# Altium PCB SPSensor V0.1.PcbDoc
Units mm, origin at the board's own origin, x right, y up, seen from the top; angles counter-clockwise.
Board outline 19.98 x 57.97 mm, 4 copper layers (TopLayer, GND, PWR, BottomLayer); 75 components, 49 nets, 242 pads, 80 vias.
Unrouted connection lines stored in the file: 11.
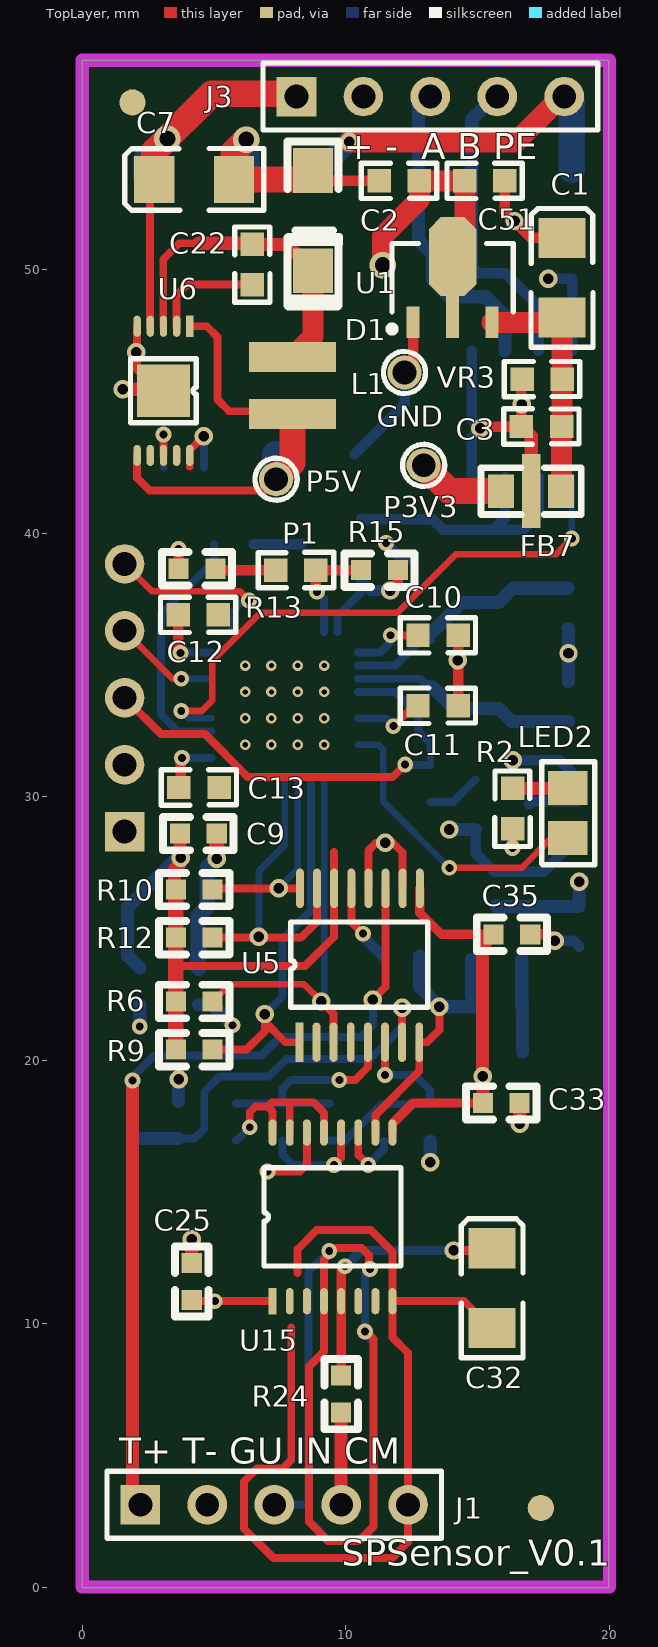
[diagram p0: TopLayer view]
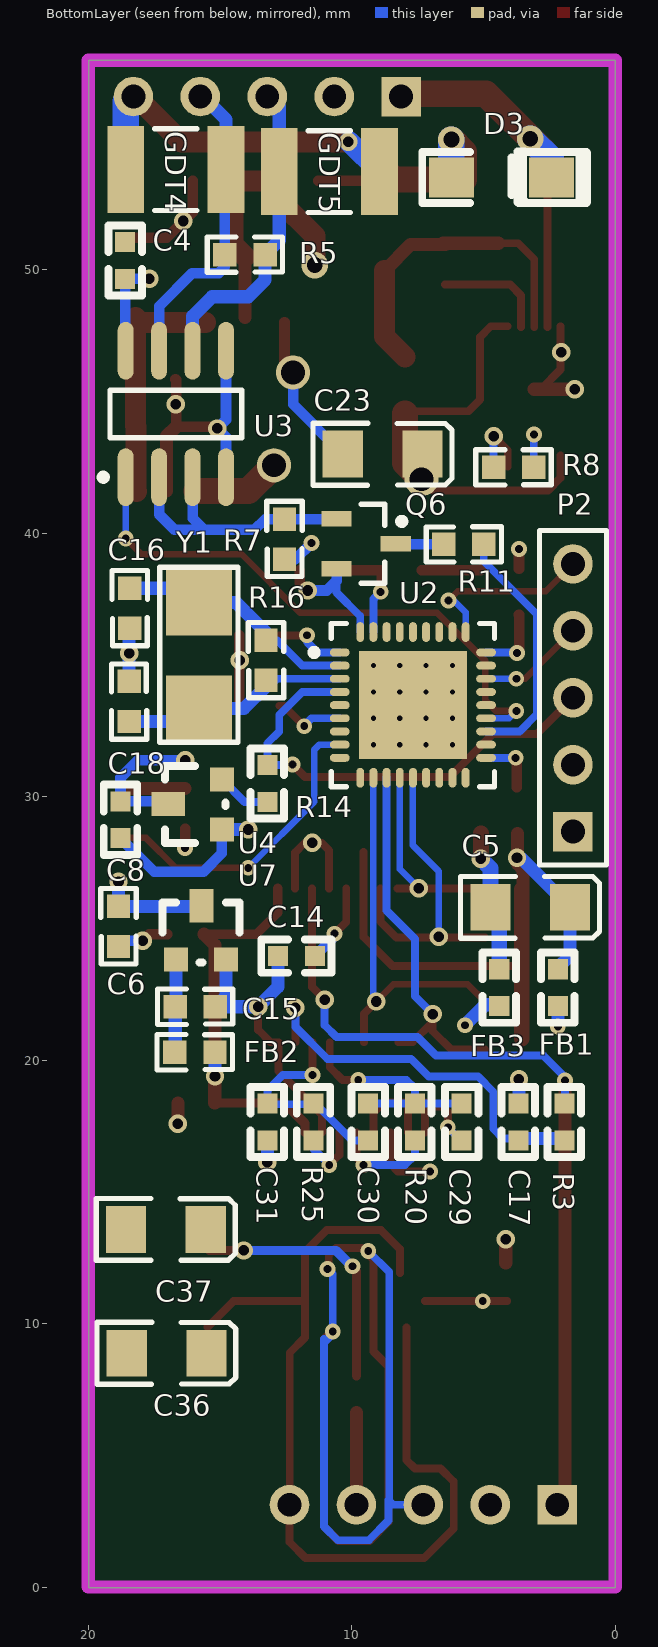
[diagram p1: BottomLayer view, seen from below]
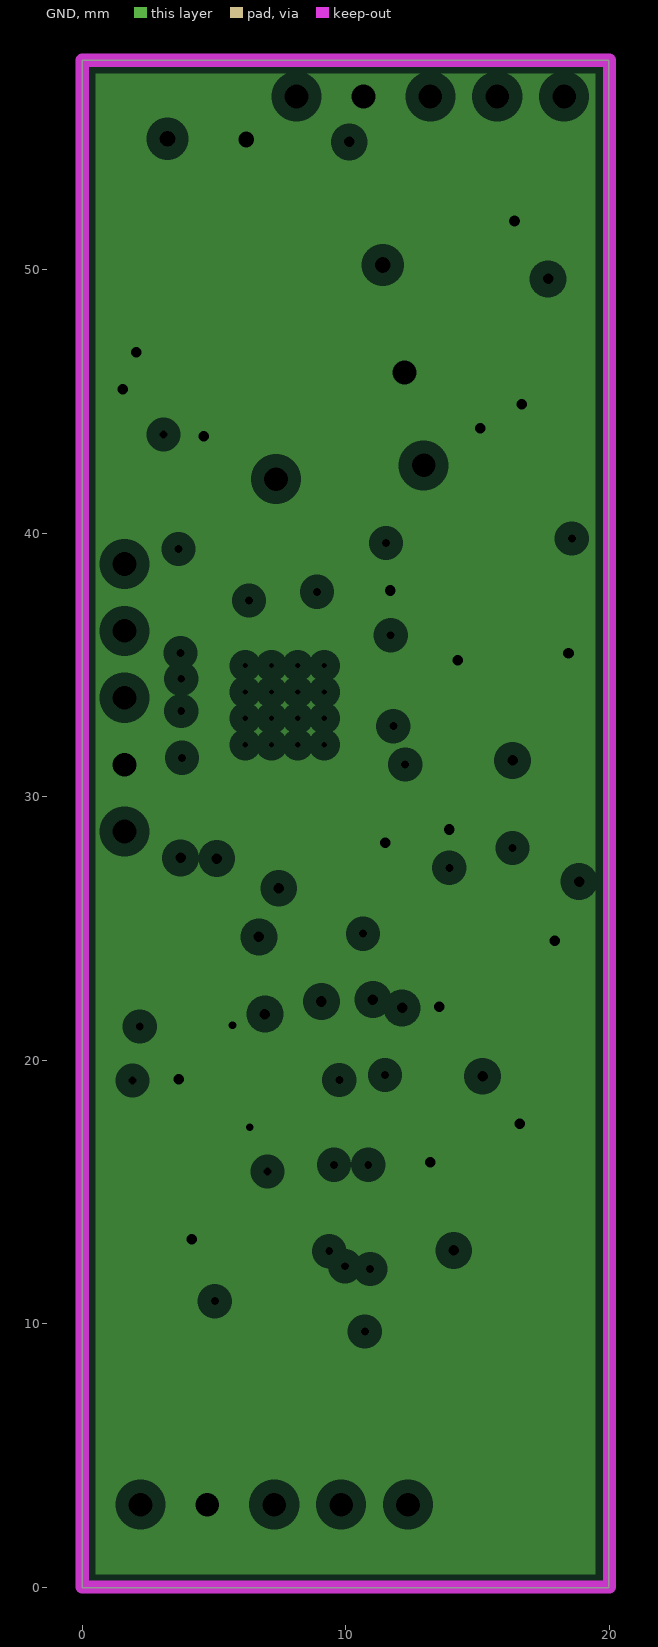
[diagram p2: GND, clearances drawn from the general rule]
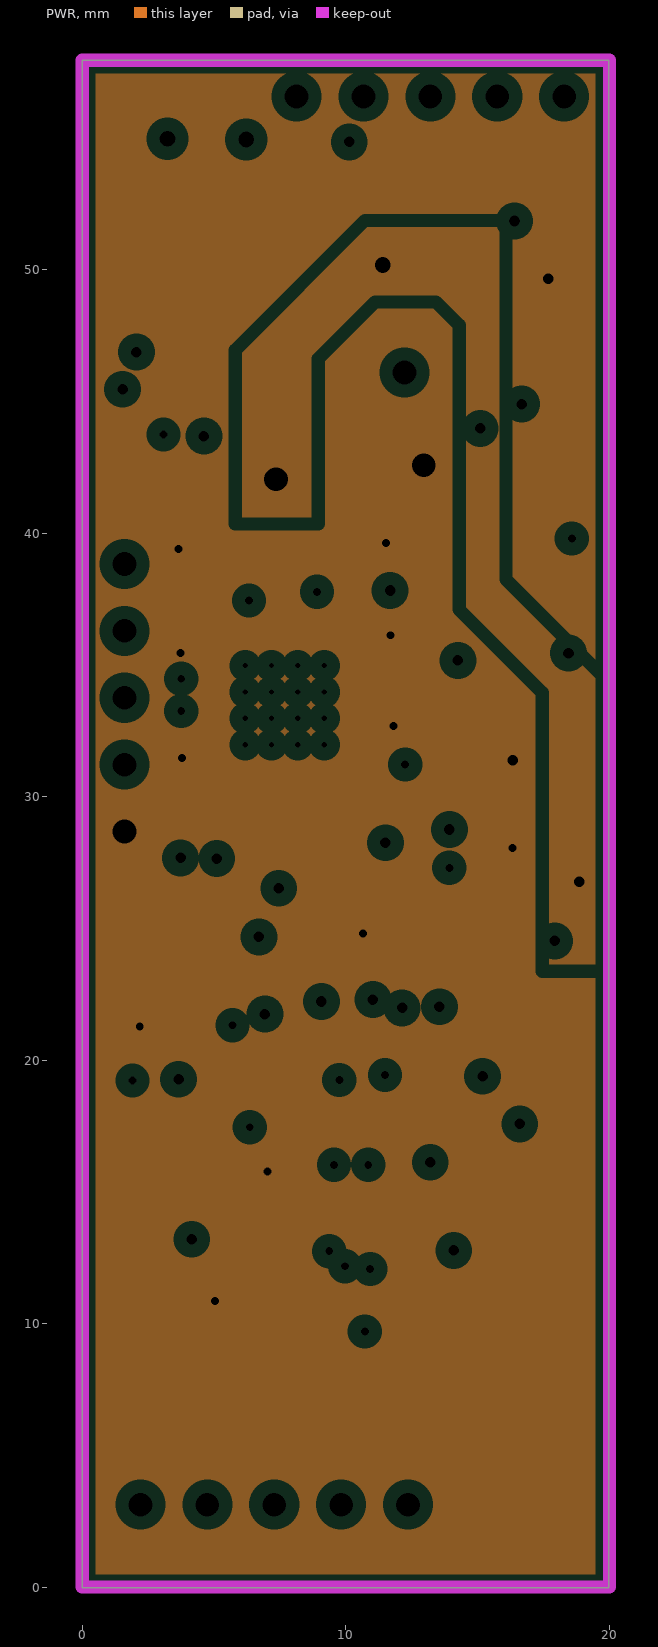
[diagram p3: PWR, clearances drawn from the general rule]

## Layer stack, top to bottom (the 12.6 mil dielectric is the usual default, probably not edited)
TopLayer: signal copper 0.0356
Dielectric: core 0.32, FR-4, Dk 4.8
GND: plane copper 0.0356, net GND
Dielectric: prepreg 0.32, FR-4, Dk 4.8
PWR: plane copper 0.0356, net VCC3.3
Dielectric: core 0.32, FR-4, Dk 4.8
BottomLayer: signal copper 0.0356

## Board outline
-0.006,-0.025 19.975,-0.025 19.975,57.95 -0.006,57.95

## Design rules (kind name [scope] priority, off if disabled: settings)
Clearance Clearance_poly [InPolygon] p1: gap=0.3
Clearance [All] p2: gap=0.15
ComponentClearance [All] p1: gap=0.15 collisioncheckmode=3 verticalgap=0.254 showdistances=FALSE
FabricationTestPointUsage TestPointUsage [All] p1: valid=0 allowmultiple=FALSE
FabricationTestpoint Testpoint [All] p1: side=3 testpointundercomponent=TRUE minsize=1.016 maxsize=2.54 preferedsize=1.524 minholesize=0.508 maxholesize=1.016 preferedholesize=0.813 testpointgrid=0.025 allowsidetop=TRUE allowsidebottom=TRUE usegrid=TRUE gridtolerance=0
HoleSize [All] p1: absolutevalues=TRUE maxlimit=5.08 minlimit=0.025 maxpercent=80.000 minpercent=20.000
MinimumSolderMaskSliver [All] p1: minsoldermaskwidth=0.15
PlaneClearance [All] p1: clearance=0.5
PlaneConnect [All] p1: planeconnectstyle=Relief reliefexpansion=0.5 reliefentries=4 reliefconductorwidth=0.3 reliefairgap=0.3
PolygonConnect PolygonConnect_via [IsVia] p1: connectstyle=Direct reliefconductorwidth=0.254 reliefentries=4 polygonreliefangle="90 Angle"
PolygonConnect [All] p2: connectstyle=Relief reliefconductorwidth=0.3 reliefentries=4 polygonreliefangle="90 Angle"
RoutingVias [All] p1: holewidth=0.305 width=0.61 viastyle="Through Hole" minholewidth=0.254 minwidth=0.508 maxholewidth=2 maxwidth=5
SilkToSilkClearance [All] p1: silktosilkclearance=0
SilkscreenOverComponentPads [All] p1: minsilkscreentomaskgap=0
SolderMaskExpansion [All] p1: expansion=0.102
Width [All] p1: maxlimit=5.08 minlimit=0.1 preferedwidth=0.254
19 further rules are at their usual default settings.

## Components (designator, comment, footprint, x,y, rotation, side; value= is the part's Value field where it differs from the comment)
C1 "10uF" SM1206 18.2,49.7 r90 top
C2 "1uF" SM0603 12.025,53.425 r0 top
C3 "1uF" SM0603 17.425,44.1 r0 top
C4 "0.1uF" 0603A 18.6,49.65 r90 bottom
C5 "10uF" SM1206 3.225,25.8 r180 bottom
C6 "0.47uF" SM0603 18.8,25.075 r270 bottom
C7 "4.7uF/50V" SM1206 4.235,53.425 r180 top
C8 "0.1uF" 0603A 18.775,29.822 r270 bottom
C9 "0.1uF" 0603A 3.7,28.6 r0 top
C10 "0.1uF" SM0603 13.5,36.175 r0 top
C11 "0.1uF" SM0603 13.5,33.5 r0 top
C12 "0.1uF" SM0603 4.4,36.95 r0 top
C13 "0.1uF" SM0603 4.425,30.4 r0 top
C14 "0.1uF" 0603A 11.4,23.95 r0 bottom
C15 "0.1uF" SM0603 15.935,22.075 r180 bottom
C16 "22pF" SM0603 18.375,37.15 r270 bottom
C17 "1uF" 0603A 3.675,16.953 r90 bottom
C18 "22pF" SM0603 18.5,33.615 r90 bottom
C22 "0.47uF" SM0603 6.4,50.2 r90 top
C23 "22uF" SM1206 8.825,43 r180 bottom
C25 "0.1uF" 0603A 4.15,10.9 r90 top
C29 "0.1uF" 0603A 5.825,16.953 r90 bottom
C30 "100pF" 0603A 9.375,18.35 r270 bottom
C31 "0.1uF" 0603A 13.2,18.35 r270 bottom
C32 "1nF/2kV" SM1206 15.55,11.35 r90 top
C33 "0.1uF" 0603A 15.2,18.375 r0 top
C35 "0.1uF" 0603A 15.6,24.775 r0 top
C36 "1nF/2kV" SM1206 17.025,8.875 r180 bottom
C37 "1nF/2kV" SM1206 17.05,13.575 r180 bottom
C51 "0.1uF" SM0603 15.275,53.425 r0 top
D1 "CD1607-B140" 1206D 8.75,53.575 r270 top
D3 "M7" 1206D 6.025,53.5 r180 bottom
FB1 "BLM18PG600SN1" 0603A 2.175,22.053 r90 bottom
FB2 "BLM18PG600SN1" SM0603 15.95,20.35 r180 bottom
FB3 "BLM18PG600SN1" 0603A 4.4,22.053 r90 bottom
FB7 "NFM21PC105B1C3" NFM21PC105 18.175,41.6 r180 top
GDT4 "SMD1812-091" 1812 16.675,53.8 r0 bottom
GDT5 "SMD1812-091" 1812 10.85,53.725 r0 bottom
GND "TestPoint" "test point" 12.225,46.1 r90 top
J1 "Header 5" HDR1X5 2.2,3.125 r0 top
J3 "Header 5" HDR1X5 8.125,56.575 r0 top
L1 "LPS3010-472ML" LPS3010 7.975,46.69 r270 top
LED2 "RUN" SM0805 18.4,29.4 r270 top
P1 "NC" sm0603 8.1,38.55 r180 top
P2 "Header 5" HDR1X5 1.6,28.675 r90 bottom
P3V3 "TestPoint" "test point" 12.95,42.575 r90 top
P5V "TestPoint" "test point" 7.35,42.05 r90 top
Q6 "MMBT3904" SOT23_N 9.45,39.6 r180 bottom
R2 "560R" SM0603 16.275,29.55 r90 top
R3 "10K" 0603A 1.925,18.35 r270 bottom
R5 "120R" SM0603 14.05,50.625 r180 bottom
R6 "100K" 0603A 3.545,22.225 r0 top
R7 "4.7K" SM0603 12.5,39.775 r270 bottom
R8 "49.9K" SM0603 3.85,42.55 r180 bottom
R9 "100K" 0603A 3.545,20.4 r0 top
R10 "100K" 0603A 3.545,26.475 r0 top
R11 "1K" SM0603 5.75,39.525 r0 bottom
R12 "100K" 0603A 3.545,24.65 r0 top
R13 "1K" 0603A 3.65,38.65 r0 top
R14 "1K" 0603A 13.2,29.8 r90 bottom
R15 "100K" 0603A 11.975,38.6 r180 top
R16 "1M" SM0603 13.2,35.175 r270 bottom
R20 "1K" 0603A 7.6,16.953 r90 bottom
R24 "1K" 0603A 9.82,6.625 r90 top
R25 "1K" 0603A 11.45,16.953 r90 bottom
U1 "RT9166A-33PXL" SOT89L 14.05,49.7 r90 top
U2 "STM32F103T8U6" VFQN36_V 7.675,33.475 r180 bottom
U3 "MAX3485CSA" NSO8_N 16.675,44.525 r90 bottom
U4 "CAT809VTBI-GT3" SOT-23 17.075,31.086 r90 bottom
U5 "AD7793BRU" AD7793 10.52,23.6 r90 top
U6 "LT3971IMSE-5" LT3971 3.075,45.405 r180 top
U7 "AD1584B" SOT-23 14.339,25.975 r180 bottom
U15 "LMP91200" LMP91200 9.495,14.05 r0 top
VR3 "V3.5MLA0603N" SM0603 17.45,45.9 r0 top (schematic designator VA2)
Y1 "8MHz" CY5.4X4.6 15.8,37.35 r270 bottom

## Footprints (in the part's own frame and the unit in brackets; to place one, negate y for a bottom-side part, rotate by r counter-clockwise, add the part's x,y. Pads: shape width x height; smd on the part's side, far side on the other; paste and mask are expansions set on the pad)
0603A [mil]
  rect 30x30 smd: 1(0,0) 2(55,0)
  silkscreen extent -25,-25 80,25
1206D [mm]
  rect 1.7x1.524 smd: 1(-0.19,0.003) 2(3.61,0.003)
  silkscreen extent -1.3,-0.97 4.96,0.99
1812 [mm] "Chip Capacitor, Body 4.5x3.2mm, IPC High Density"
  rect 1.4x3.3 smd: 1(-1.9,0) 2(1.9,0)
  silkscreen extent -0.8,-1.55 0.8,1.55, body extent -2.4,-1.7 2.4,1.7, height 1.4
AD7793 [mm]
  rect 1.5x0.3 smd: 1(-2.921,2.286)
  oval 1.5x0.3 smd: 2(-2.921,1.636) 3(-2.921,0.986) 4(-2.921,0.336) 5(-2.921,-0.314) 6(-2.921,-0.964) 7(-2.921,-1.614) 8(-2.921,-2.264) 9(2.921,-2.286) 10(2.921,-1.636) 11(2.921,-0.986) 12(2.921,-0.336) 13(2.921,0.314) 14(2.921,0.964) 15(2.921,1.614) 16(2.921,2.264)
  silkscreen extent -1.59,-2.59 1.64,2.61
CY5.4X4.6 [mm]
  rect 2.5x2.5 smd: 1(-0.025,0) 2(4,0)
  silkscreen extent -1.35,-1.49 5.28,1.49
HDR1X5 [mm] "Connector; Header; 5 Position"
  rect 1.5x1.5 hole 0.9: 1(0,0)
  round 1.5 hole 0.9: 2(2.54,0) 3(5.08,0) 4(7.62,0) 5(10.16,0)
  silkscreen extent -1.27,-1.27 11.43,1.27
LMP91200 [mm]
  rect 0.3x1 smd: 1(-2.275,-3.2)
  oval 0.3x1 smd: 2(-1.625,-3.2) 3(-0.975,-3.2) 4(-0.325,-3.2) 5(0.325,-3.2) 6(0.975,-3.2) 7(1.625,-3.2) 8(2.275,-3.2) 9(2.275,3.2) 10(1.625,3.2) 11(0.975,3.2) 12(0.325,3.2) 13(-0.325,3.2) 14(-0.975,3.2) 15(-1.625,3.2) 16(-2.275,3.2)
  silkscreen extent -2.6,-1.87 2.6,1.87
LPS3010 [mm]
  rect 1.14x3.3 smd: 1(0,0) 2(2.16,0)
LT3971 [mm]
  rect 0.28x0.8 smd: 1(-1,-2.45)
  oval 0.28x0.8 smd: 2(-0.5,-2.45) 3(0,-2.45) 4(0.5,-2.45) 5(1,-2.45) 6(1,2.45) 7(0.5,2.45) 8(0,2.45) 9(-0.5,2.45) 10(-1,2.45)
  rect 2x2 smd: 11(0,0)
  silkscreen extent -1.25,-1.21 1.25,1.22
NFM21PC105 [mm]
  rect 1x1.27 smd: 1(0.01,0.008) 2(2.286,0)
  rect 0.7x2.8 smd: 3(1.143,0)
  silkscreen extent -0.76,-0.89 3.05,0.89
NSO8_N [mm] "SOIC, 8-Leads, Body 4.9x3.9mm, Pitch 1.27mm, IPC Medium Density"
  oval 2.2x0.6 smd: 1(-2.4,1.905) 2(-2.4,0.635) 3(-2.4,-0.635) 4(-2.4,-1.905) 5(2.4,-1.905) 6(2.4,-0.635) 7(2.4,0.635) 8(2.4,1.905)
  silkscreen extent -2.52,-2.5 0.9,2.88, body extent -2,-2.5 2,2.5, height 1.75
SM0603 [mil]
  rect 35x35 smd: 1(-30,-2) 2(30,-2)
  silkscreen extent -57,-28 56,24
sm0603 [mil]
  rect 35x35 smd: 1(-30,-2) 2(30,-2)
  silkscreen extent -57,-28 56,24
SM0805 [mm]
  rect 1.3x1.5 smd: 1(-0.933,0.022) 2(0.967,0.022)
  silkscreen extent -1.93,-0.97 1.98,1.04
SM1206 [mil]
  rect 60x70 smd: 1(59.5,0) 2(-59.5,0)
  silkscreen extent -104,-46 104,46
SOT23_N [mm] "SOT23, 3-Leads, Body 2.9x1.3mm, Pitch 0.95mm, Lead Span 2.3mm - Reverse Pinning, IPC Medium Density"
  rect 1.15x0.6 smd: 1(1.125,0) 2(-1.125,-0.95) 3(-1.125,0.95)
  silkscreen extent -0.2,-1.5 1.47,1.5, body extent -0.7,-1.5 0.7,1.5, height 1.1
SOT89L [mm] "SOT89, 3-Leads, Body 4.5x2.4 mm, Pitch 1.5mm, Lead Span 4.1mm, IPC High Density"
  rect 1.2x0.5 smd: 1(-1.7,1.5) 3(-1.7,-1.5)
  rect 1.6x0.5 smd: 2(-1.5,0)
  oct 3x1.8 smd: 2(0.8,0)
  silkscreen extent -2.07,-2.3 1.3,2.42, body extent -1.3,-2.3 1.3,2.3, height 1.6
SOT-23 [mil]
  rect 36x36 smd: 1(-91.86,-84.66) 2(-16.86,-84.66)
  rect 36x50 smd: 3(-53.86,-4.66)
  silkscreen extent -112,-90 3,0
"test point" [mm]
  round 1.3 hole 0.9: 1(0,0)
  silkscreen extent -0.8,-0.8 0.8,0.8
VFQN36_V [mm] "QFN, 36-Leads, Body 6x6mm, Pitch 0.5mm, ST Recommended"
  oval 0.75x0.3 smd: 1(-2.775,2) 2(-2.775,1.5) 3(-2.775,1) 4(-2.775,0.5) 5(-2.775,0) 6(-2.775,-0.5) 7(-2.775,-1) 8(-2.775,-1.5) 9(-2.775,-2) 19(2.775,-2) 20(2.775,-1.5) 21(2.775,-1) 22(2.775,-0.5) 23(2.775,0) 24(2.775,0.5) 25(2.775,1) 26(2.775,1.5) 27(2.775,2)
  oval 0.3x0.75 smd: 10(-2,-2.755) 11(-1.5,-2.755) 12(-1,-2.755) 13(-0.5,-2.755) 14(0,-2.755) 15(0.5,-2.755) 16(1,-2.755) 17(1.5,-2.755) 18(2,-2.755) 28(2,2.775) 29(1.5,2.775) 30(1,2.775) 31(0.5,2.775) 32(0,2.775) 33(-0.5,2.775) 34(-1,2.775) 35(-1.5,2.775) 36(-2,2.775)
  rect 4.1x4.1 smd: 37(0,0)
  silkscreen extent -3.88,-3.1 3.1,3.1, body extent -3.05,-3.05 3.05,3.05, height 1

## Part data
C1 C2 C3 C10 C11 C12 C13 C16 C18: library part Cap, "Capacitor"
C4 C8: library part Cap, "Capacitor, X7R Ceramic"
C5: library part CAPE, "¼«Ð"
C6 C9 C14 C15 C22 C25 C29 C30 C31 C32 C33 C35 C36 C37 C51: library part CAP, "Capacitor"
C7 C23: library part C, "¼«Ð"
C17: library part CAP, "电?"
D1: library part DIODE, "Diode"
D3: library part "Diode 1N4007", "1 Amp General Purpose Rectifier"
FB1 FB3 L1: library part INDUCTOR
FB2 FB7: library part Inductor, "Inductor"
GDT4 GDT5: library part BT90
J1 J3 P2: "Header, 5-Pin"
LED2: library part LED0, "Typical INFRARED GaAs LED"
P1: library part Header, "Header, 2-Pin, 2.54mm, 排?"
Q6: "NPN Switching Transistor"
R2 R5 R7 R11 R16: library part Res2, "Resistor"
R3 R6 R9 R10 R12 R20 R24 R25: library part RES, "电?"
R8 R13 R14 R15: library part RE, "电?"
U1: library part "Header 3", "Header, 3-Pin"
U2: "STM32 ARM-based 32-bit MCU with 64 Kbytes Flash, 36-pin VFQFPN, Industrial Temperature"
U3: library part MAX485CSA, "Low-Power, Slew-Rate-Limited RS-485/RS-422 Transceiver"
U4: library part CAT809-SOT, "Onsemi"
U5: library part AD7793
U6: library part LT3971
U7: library part "Header 3", "4.096V reference"
VR3: library part "D Zener", "Zener Diode"
Y1: library part XTAL, "Crystal Oscillator"

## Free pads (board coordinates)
  round 1 smd: 0(1.9,56.35) 0(17.4,3)

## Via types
v1: diameter 0.7, hole 0.4, TopLayer to BottomLayer, 31 vias
v2: diameter 0.6, hole 0.3, TopLayer to BottomLayer, 30 vias
v3: diameter 0.4, hole 0.2, TopLayer to BottomLayer, tented top, 16 vias
v4: diameter 1, hole 0.6, TopLayer to BottomLayer, 3 vias

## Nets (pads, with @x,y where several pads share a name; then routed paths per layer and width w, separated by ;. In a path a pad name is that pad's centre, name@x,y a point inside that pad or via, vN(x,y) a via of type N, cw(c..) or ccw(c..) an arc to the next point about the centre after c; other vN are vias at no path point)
+24V: C7.1 D3.2 J3.1 U6.4 | length 14.8
  TopLayer w0.3: U6.4@2.569,47.823 2.569,53.27 C7.1
  TopLayer w1: C7.1 2.724,54.499 4.9,56.675 J3.1@8.125,56.675
  BottomLayer w1: D3.2 2.415,54.165 v4(3.225,54.975)
BOOT0: P1.1 R15.2 U2.35 | length 4.1
  TopLayer w0.4: v2@8.862,37.813 P1.1 R15.2@10.577,38.601
  BottomLayer w0.3: v2(8.9,37.775) 9.175,37.5 U2.35
DVDD: C5.1 C9.1 FB1.2 R6.1 R9.1 R10.1 R12.1 U5.14 | length 22.8
  TopLayer w0.3: 3.545,23.575 8.45,23.575 9.556,24.681 U5.14 9.556,27.894
  TopLayer w0.5: R10.1 3.5,26.519 3.5,27.25 3.7,27.45 C9.1
  TopLayer w0.6: 3.545,20.825 3.545,23.575 R10.1
  BottomLayer w0.5: FB1.2@2.175,23.5 1.714,23.961 C5.1 3.589,27.675 v1(3.725,27.675)
EARTH: GDT4.2 GDT5.1 J3.5 | length 13.5
  TopLayer w0.8: v1(10.125,54.85) 16.46,54.85 J3.5@18.285,56.675
  BottomLayer w0.8: GDT5.1 v1@10.075,54.85
  BottomLayer w1: J3.5@18.285,56.675 18.575,56.385 GDT4.2
GND: C1.1 C2.1 C3.1 C4.2 C6.2 C7.2 C8.2 C10.2 C11.2 C12.2 C13.2 C14.2 C15.2 C16.2 C17.2 C18.2 C23.2 C25.2 C29.1 C31.2 C33.2 C35.2 C36.2 C37.2 C51.2 D1.1 D3.1 FB3.1 FB7.3 GND.1 J1.2 J3.2 P2.2 Q6.2 R8.1 R15.1 U1.1 U2.5 U2.17 U2.18 U2.26 U2.36 U3.4 U3.5 U4.1 U5.8 U5.10 U5.12 U6.5 U6.10 U6.11 U7.2 U15.10 U15.13 U15.15 U15.16 VR3.1 | length 83.4
  TopLayer w0.3: U6.5 2.075,46.216 U6.11@2.825,45.465 ; 4.075,42.53 U6.10 4.075,43.15 v1(4.612,43.687) ; v2(6.35,17.451) 6.35,18.025 6.558,18.233 7.033,18.233 ; U15.16 7.22,18.047 7.033,18.233 ; U15.15 7.87,18.325 7.795,18.4 ; U15.13 9.17,18 8.77,18.4 7.795,18.4 ; U5.12 10.856,27.956 11.15,28.25 v1(11.5,28.25) 11.781,28.25 12.156,27.875 U5.10 ; U15.10 11.12,17.92 12.784,19.584 U5.8 13.079,20.679 13.55,21.15 v1(13.55,22.025) ; 7.033,18.233 7.2,18.4 7.795,18.4
  TopLayer w0.4: D1.1 9.144,53.374 C2.1 ; v1(11.675,37.825) 11.975,38.125 R15.1 ; GND.1 12.55,46.425 U1.1 ; C11.2 C10.2 ; v1(15.1,43.975) 15.174,44.049 C3.1 16.663,45.824 VR3.1 ; C51.2 16.037,52.188 17.014,51.211 C1.1 ; C35.2 17.675,24.775 v1(17.925,24.525)
  TopLayer w0.5: v1@1.487,45.465 v1(1.525,45.465) 2.825,45.465 U6.11@3.069,45.465 ; C25.2 v1(4.15,13.2) ; v1(16.597,17.578) C33.2 ; C3.1 17.032,43.68 FB7.3
  TopLayer w1: v4(6.215,54.94) 5.747,54.472 C7.2 8.412,53.425 D1.1
  BottomLayer w0.3: R8.1 v1(4.612,43.687) ; C29.1 5.852,16.953 v2(6.35,17.451) ; U2.36 9.675,36.85 10.575,37.75 10.575,38.2
  BottomLayer w0.4: C23.2 12.225,44.889 GND.1 ; Q6.2 10.575,38.2 10.95,37.825 v1(11.675,37.825) ; U3.4 14.77,43.645 v1(15.1,43.975) 14.77,44.305 U3.5 ; U4.1 14.925,27.85 15.625,27.15 17.5,27.15 C8.2 ; v1(17.925,24.525) 18.639,24.525 C6.2
  BottomLayer w0.5: C17.2@3.65,18.425 v1(3.65,19.275) ; FB3.1@4.4,22.1 4.925,22.1 v2(5.7,21.325) ; C14.2 12.797,22.778 v1(13.55,22.025) C15.2@15.172,22.025 ; v1(13.2,16.125) C31.2@13.2,16.925 ; v1(13.928,28.753) U4.1 ; U7.2 14.767,22.43 C15.2@15.172,22.025 ; C15.2 C15.2@15.172,22.025 ; C16.2 18.449,36.365 v1(18.449,35.45) C18.2
  BottomLayer w1: D3.1 v4(6.215,54.94)
  other v1: 14.25,35.175 16.675,44.9 2.05,46.875 16.4,51.85
GUARD: J1.3 U15.4 | length 48.3
  TopLayer w0.3: v2@10.695,9.775 11.05,9.419 11.05,2.3 10.5,1.75 9.325,1.75 8.6,2.475 8.6,8.375 9.17,8.945 U15.4 9.17,12.425 9.62,12.875 10.595,12.875 10.87,12.6 v2@10.87,12
  BottomLayer w0.3: J1.3 8.425,3.125 8.575,3.275 8.575,11.955 v2(9.37,12.75) ; 8.6,3.3 8.6,2.525 9.35,1.775 10.525,1.775 11.05,2.3 11.05,9.419 ; v2@10.72,9.6 11.05,9.269 ; v2(10.72,9.7) 10.72,11.875 v2(10.92,12.075)
JTCK: P2.5 U2.28 | length 7.3
  TopLayer w0.25: P2.5 2.635,37.8 5.975,37.8 v2(6.325,37.45)
  BottomLayer w0.25: P2.5@1.6,38.425 P2.5 ; U2.28 5.675,37 6.125,37.45 v2(6.325,37.45)
JTDI: U2.29
JTDO: U2.30
JTMS: P2.4 U2.25 | length 4.1
  TopLayer w0.25: P2.4 3.42,34.475 v2(3.75,34.475)
  BottomLayer w0.25: v2(3.75,34.475) U2.25
JTRST: U2.31
LED_S1: U2.23
LED_S2: LED2.2 U2.8 | length 11.5
  TopLayer w0.25: v2(13.925,27.3) 16.675,27.3 17.808,28.433 LED2.2
  BottomLayer w0.25: U2.8 11.225,31.975 11.425,31.775 11.425,29.8 v2(13.925,27.3)
MCU_RXD1: U2.22 U3.1 | length 22
  TopLayer w0.25: v2(3.75,33.25) 4.525,33.25 4.925,33.65 4.925,35.15 6.75,36.975 11.95,36.975 14.175,39.2 17.975,39.2 v2(18.575,39.8)
  BottomLayer w0.25: v2(3.75,33.25) 4.025,32.975 U2.22 ; v2(18.575,39.8) 18.58,39.805 U3.1
MCU_TXD1: R11.1 U2.21 | length 9.5
  BottomLayer w0.3: U2.21 3.625,32.475 2.975,33.125 2.975,36.925 4.988,38.938 R11.1
MISO1: R12.2 U2.14 U5.15 | length 11.9
  TopLayer w0.3: R12.2 8.3,24.65 8.906,25.256 U5.15
  BottomLayer w0.25: v1(6.7,24.675) 6.7,27.175 7.675,28.15 U2.14
MOSI1: R10.2 U2.13 U5.16 | length 7.8
  TopLayer w0.3: R10.2@4.988,26.521 U5.16
  BottomLayer w0.25: v1(7.45,26.525) 8.175,27.25 U2.13
NetC1_2: C1.2 C3.2 FB7.1 U1.3 VR3.2 | length 9.3
  TopLayer w0.8: U1.3 18.011,48 C1.2 18.2,44.062 C3.2 18.187,41.614 FB7.1
NetC5_2: C5.2 C9.2 FB3.2 | length 5.4
  TopLayer w0.6: v1@5.097,27.653 C9.2
  BottomLayer w0.6: FB3.2@4.4,23.497 4.4,25.464 C5.2 4.736,27.286 v1(5.1,27.65)
NetC15_1: C15.1 FB2.1 U7.1 | length 3.5
  BottomLayer w0.5: U7.1 16.672,22.049 C15.1 FB2.1@16.697,20.314
NetC16_1: C16.1 R16.1 U2.2 Y1.1 | length 9.1
  BottomLayer w0.3: U2.2 11.875,34.975 12.837,35.937 R16.1
  BottomLayer w0.5: R16.1@13.251,36.226 14.4,37.375 Y1.1 16.337,37.912 C16.1
NetC17_1: C17.1 R3.2 U5.7 | length 14.8
  TopLayer w0.3: U5.7 v1(12.134,21.984)
  BottomLayer w0.3: C17.1@3.65,17.028 4.253,17.028 4.625,17.4 4.625,18.8 5.2,19.375 7.075,19.375 7.75,20.05 10.925,20.05 12.134,21.259 v1(12.134,21.984)
  BottomLayer w0.5: R3.2@1.903,17.028 C17.1@3.65,17.028
NetC18_1: C18.1 R16.2 U2.3 Y1.2 | length 8.7
  BottomLayer w0.3: U2.3 12.835,34.475 13.023,34.287 R16.2@13.251,34.287
  BottomLayer w0.5: R16.2@13.251,34.187 14.088,33.35 Y1.2 ; Y1.2@15.763,33.313 Y1.2 ; C18.1 16.297,32.853 Y1.2
NetC22_1: C22.1 U6.2 | length 4.3
  TopLayer w0.3: U6.2@3.569,47.823 3.569,49.024 3.982,49.438 C22.1
NetC22_2: C22.2 D1.2 L1.1 U6.3 | length 12.6
  TopLayer w0.3: U6.3@3.069,47.823 3.069,50.399 3.677,51.008 4.425,51.008
  TopLayer w0.5: 4.425,51.008 C22.2@6.525,51.008 ; C22.2 7.756,50.962 D1.2
  TopLayer w0.8: L1.1 8.753,47.468 D1.2
NetC29_2: C29.2 C30.1 R20.2 U5.5 | length 8.6
  TopLayer w0.3: v2(9.75,19.25) 10.35,19.25 10.834,19.734 U5.5
  BottomLayer w0.3: C29.2 R20.2 ; C30.1 R20.2 ; v2(9.75,19.25) 7.925,19.25 7.6,18.925 R20.2
NetC30_2: C30.2 C31.1 R25.2 U5.6 | length 8.4
  TopLayer w0.3: v2(11.484,19.434) U5.6
  BottomLayer w0.3: C30.2 9.978,16.953 11.35,18.325 11.45,18.325 C31.1@13.197,18.325 ; v2(11.484,19.434) 12.616,19.434 13.197,18.853 C31.1@13.197,18.325 ; C31.1@13.2,18.567 13.2,18.322 C31.1@13.197,18.325
NetC32_1: C32.1 C37.1 R24.2 U15.5 | length 9.9
  TopLayer w0.35: R24.2 U15.5 9.82,12 9.97,12.15 v2(9.97,12.175) ; v1(14.095,12.775) C32.1@15.4,12.775
  BottomLayer w0.35: v2(9.97,12.175) 9.97,12.15 10.595,12.775 v1(14.095,12.775)
NetLED2_1: LED2.1 R2.2 | length 2.1
  TopLayer w0.5: R2.2 18.401,30.312 LED2.1
NetP1_2: P1.2 R13.2 | length 2.3
  TopLayer w0.4: R13.2 5.096,38.601 P1.2
NetQ6_1: Q6.1 R11.2 | length 1.8
  BottomLayer w0.4: R11.2 8.301,39.576 Q6.1
NetQ6_3: Q6.3 R7.1 U3.2 U3.3 | length 10.8
  BottomLayer w0.4: Q6.3 10.588,40.537 R7.1 13.288,40.537 13.7,40.125 15.6,40.125 ; U3.3 16.04,40.565 15.6,40.125 ; U3.2 17.31,40.71 16.725,40.125 15.6,40.125
NetR8_2: R8.2 U6.8 | length 2.1
  TopLayer w0.3: U6.8 v2(3.075,43.75)
  BottomLayer w0.3: v2(3.075,43.75) 3.088,43.737 R8.2
NetR14_1: R14.1 U4.2 | length 2.1
  BottomLayer w0.3: R14.1 14.066,29.8 U4.2
NetR20_1: R20.1 U15.12 | length 4
  TopLayer w0.3: v2(9.55,16.025) 9.82,16.295 U15.12
  BottomLayer w0.3: R20.1 7.6,16.4 7.975,16.025 v2(9.55,16.025)
NetR25_1: R25.1 U15.11 | length 2.5
  TopLayer w0.3: U15.11 10.47,16.405 v2(10.85,16.025)
  BottomLayer w0.3: v2(10.85,16.025) 11.45,16.625 R25.1@11.45,16.928
PH-CMP: C32.2 C36.1 J1.5 U15.8 | length 37.8
  TopLayer w0.3: 7.925,9.85 7.925,4.825 7.6,4.5 6.625,4.5 6.125,4 6.125,2.225 7.25,1.1 11.75,1.1 12.35,1.7 ; 8.17,11.925 8.17,12.825 8.895,13.55 10.945,13.55 11.77,12.725 U15.8 ; J1.5 12.36,1.71 12.35,1.7 ; C32.2@15.475,9.864 14.489,10.85 U15.8 ; U15.8 11.77,9.475 12.35,8.895 12.35,1.7
PH-INP: J1.4 R24.1 | length 3.5
  TopLayer w0.5: J1.4 R24.1
RS485+: GDT5.2 J3.3 R5.2 U3.6 | length 12.1
  BottomLayer w0.5: J3.3@13.205,56.675 12.75,56.22 GDT5.2 12.75,51.112 R5.2 13.288,49.612 13.925,48.975 15.3,48.975 16.04,48.235 U3.6
RS485-: GDT4.1 J3.4 R5.1 U3.7 | length 11.8
  BottomLayer w0.4: GDT4.1 14.812,53.763 R5.1 14.812,50.113 15.05,49.875 16.05,49.875 17.31,48.615 U3.7
  BottomLayer w0.5: GDT4.1 14.775,55.705 J3.4@15.745,56.675
RST#: P2.3 R14.2 U2.4 | length 17.8
  TopLayer w0.3: P2.3 2.98,32.375 4.65,32.375 6.275,30.75 11.775,30.75 v2(12.25,31.225)
  BottomLayer w0.3: U2.4 11.875,33.975 12.75,33.1 12.75,32.475 13.2,32.025 R14.2 12.278,31.197 v2(12.25,31.225)
RX485: U2.10
SCK1: R9.2 U2.12 U5.1 | length 14.5
  TopLayer w0.3: R9.2 6.225,20.4 6.925,21.1 v1(6.925,21.75) 6.925,21.45 7.696,20.679 U5.1
  BottomLayer w0.3: v1(6.925,21.75) 7.6,22.425 7.6,24.6 8.675,25.675 U2.12
SSEL1: R6.2 U2.11 U5.3 | length 14.9
  TopLayer w0.25: R6.2 5.592,22.875 8.419,22.875 v1(9.07,22.225)
  TopLayer w0.3: v1(9.07,22.225) 9.534,21.761 U5.3
  BottomLayer w0.25: v1(9.07,22.225) 9.175,22.33 U2.11
TP-IN+: J1.1 R3.1 U5.11 | length 32.5
  TopLayer w0.3: v1(11.025,22.3) 11.506,22.781 U5.11
  TopLayer w0.5: v2(1.9,19.225) 1.9,3.425 J1.1
  BottomLayer w0.3: R3.1@1.9,18.422 v2(1.9,19.225) 1.9,19.35 2.725,20.175 6.8,20.175 7.5,20.875 10.575,20.875 11.025,21.325 v1(11.025,22.3)
TX485: U2.9
VCC3.3: C4.1 C8.1 C10.1 C11.1 C12.1 C13.1 C14.1 C25.1 FB1.1 FB7.2 P2.1 P3V3.1 R2.1 R7.2 R13.1 U2.1 U2.6 U2.19 U2.27 U3.8 U4.3 U5.13 U15.1 U15.14 | length 35.3
  TopLayer w0.3: C25.1@4.095,10.85 U15.1 ; v2(7.025,15.775) 8.25,15.775 8.52,16.045 U15.14 ; U5.13 10.206,25.244 v2(10.65,24.8) ; v2(11.7,36.125) 11.701,36.124 C10.1 ; v2(11.8,32.675) 12.574,33.449 C11.1
  TopLayer w0.4: C12.1@3.65,36.911 C12.1 3.638,35.537 v2(3.725,35.45) ; R13.1 v2(3.65,39.4) ; C13.1@3.738,30.349 3.738,31.438 v2(3.775,31.475) ; v2(16.326,28.051) R2.1
  TopLayer w1: P3V3.1 13.925,41.6 FB7.2
  BottomLayer w0.3: v2(3.725,35.45) 3.7,35.475 U2.27 ; v2(3.775,31.475) U2.19 ; U2.6 11.525,32.975 11.8,32.7 v2(11.8,32.675) ; U2.1 11.3,35.475 v2@11.675,35.85
  BottomLayer w0.4: v2(10.65,24.8) 10.65,24.7 C14.1 ; v2(11.525,39.625) 12.137,39.013 R7.2 ; v1(16.325,31.375) 18.125,31.375 18.775,30.725 C8.1 17.06,29.822 U4.3 ; v1(17.675,49.65) C4.1 18.6,46.945 U3.8
  BottomLayer w0.5: v2(2.175,21.275) FB1.1@2.175,22.103
  other v2: 5.025,10.85
VCC5: C2.2 C6.1 C23.1 C51.1 L1.2 P5V.1 U1.2 U6.1 U6.6 U7.3 | length 31.8
  TopLayer w0.3: U6.6 2.075,42.1 2.55,41.625 6.925,41.625 P5V.1 ; U6.1 4.719,47.855 5.125,47.45 5.125,45.075 5.569,44.63 L1.2@7.975,44.63
  TopLayer w0.5: U1.2@14.05,48.2 U1.2@14.05,50.5
  TopLayer w0.8: v4(11.4,50.175) 11.4,51.275 12.787,52.662 C2.2 C51.1 14.513,50.963 U1.2@14.05,50.5
  TopLayer w1: P5V.1 7.975,42.675 L1.2
  BottomLayer w0.5: U7.3 15.726,25.837 C6.1 v1(18.851,26.774)
  BottomLayer w1: C23.1 7.314,42.086 P5V.1
VREF: C33.1 C35.1 FB2.2 U5.9 U15.9 | length 15.6
  TopLayer w0.35: U15.9 11.77,17.595 12.55,18.375 C33.1 ; U5.9 12.806,25.594 13.625,24.775 C35.1
  TopLayer w0.5: v1(15.188,19.387) 15.188,24.363 C35.1 ; C33.1 v1@15.2,19.375
  BottomLayer w0.5: v1(15.188,19.387) FB2.2
pads on no net: U2.7 U2.15 U2.16 U2.20 U2.24 U2.32 U2.33 U2.34 U2.37 U5.2 U5.4 U6.7 U6.9 U15.2 U15.3 U15.6 U15.7
copper on no net:
  other v3: 6.175,31.975 7.175,31.975 8.175,31.975 9.175,31.975 6.175,32.975 7.175,32.975 8.175,32.975 9.175,32.975 6.175,33.975 7.175,33.975 8.175,33.975 9.175,33.975 6.175,34.975 7.175,34.975 8.175,34.975 9.175,34.975

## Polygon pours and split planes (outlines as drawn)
GND on GND (split plane): 19.465,0.485 0.505,0.485 0.505,57.44 19.465,57.44
VCC5 on PWR (split plane): 15.823,38.25 15.831,38.185 15.857,38.124 15.897,38.072 19.465,34.504 19.465,23.627 17.702,23.627 17.702,33.95 17.694,34.015 17.668,34.076 17.646,34.106 17.628,34.128 14.552,37.204 14.552,47.9 14.544,47.965 14.526,48.008 14.518,48.026 14.501,48.049 14.478,48.078 13.603,48.953 13.551,48.993 13.49,49.019 13.425,49.027 11.1,49.027 11.035,49.019 10.974,48.993 10.922,48.953 8.772,46.803 8.732,46.751 8.706,46.69 8.698,46.625 8.698,40.602 6.052,40.602 6.052,46.846 10.829,51.623 15.823,51.623
VCC3.3 on PWR (split plane): 19.465,35.217 16.327,38.354 16.327,51.875 16.319,51.94 16.293,52.001 16.253,52.053 16.201,52.093 16.14,52.119 16.075,52.127 10.725,52.127 10.66,52.119 10.599,52.093 10.547,52.053 5.622,47.128 5.582,47.076 5.556,47.015 5.548,46.95 5.548,40.35 5.556,40.285 5.582,40.224 5.622,40.172 5.674,40.132 5.735,40.106 5.8,40.098 8.95,40.098 9.015,40.106 9.076,40.132 9.128,40.172 9.168,40.224 9.194,40.285 9.202,40.35 9.202,46.521 11.204,48.523 13.321,48.523 14.048,47.796 14.048,37.1 14.056,37.035 14.082,36.974 14.122,36.922 17.198,33.846 17.198,23.375 17.206,23.31 17.232,23.249 17.272,23.197 17.324,23.157 17.385,23.131 17.45,23.123 19.465,23.123 19.465,0.485 0.505,0.485 0.505,57.44 19.465,57.44

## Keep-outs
KeepOutLayer:
  lines w0.5: -0.006,0 10.994,0 20,0 20,57.95 -0.006,57.95 -0.006,0

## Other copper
PWR (plane layer: these items are gaps in the copper):
  lines w0.5: 5.8,40.35 5.8,46.95 10.725,51.875 16.075,51.875 16.075,38.25 19.975,34.35 19.975,23.375 17.45,23.375 17.45,33.95 14.3,37.1 14.3,47.9 13.425,48.775 11.1,48.775 8.95,46.625 8.95,40.35 5.8,40.35

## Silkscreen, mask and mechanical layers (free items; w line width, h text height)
TopOverlay:
  text "+ -  A B PE" at 9.925,54.2 h1
  text "T+ T- GU IN CM" at 1.4,4.675 h1
  text "SPSensor_V0.1" at 9.85,0.8 h1
Mechanical1:
  lines w0.3: -1.725,57.95 21.8,57.95 ; -1.206,3.075 26.45,3.075 ; -0.431,0.025 31.15,0.025 ; 0.006,4.125 0.006,78.075 ; 19.981,-1.325 19.981,62

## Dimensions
21.125,57.95 to 20.794,-0.016 on Mechanical1
-0.006,4.75 to 19.975,-0.975 on Mechanical1
-0.75,3.075 to -0.85,0.025 on Mechanical1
